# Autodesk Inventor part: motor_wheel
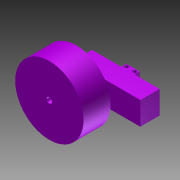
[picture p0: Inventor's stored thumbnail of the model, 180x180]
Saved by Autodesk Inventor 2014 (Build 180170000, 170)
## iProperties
Created: 2015-06
Part Number: motor_wheel
Material: Generic
Document SubType Name: Modeling
Designer: common
Density: 1 g/cm^3
Appearance: Default
Author: common
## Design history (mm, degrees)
node "motor_wheel.ipt1"
body "Solid2"
node "Base1"
